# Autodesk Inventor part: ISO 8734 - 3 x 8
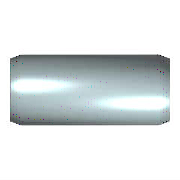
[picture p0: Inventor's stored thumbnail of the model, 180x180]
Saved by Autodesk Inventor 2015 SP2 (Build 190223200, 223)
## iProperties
Created: 2012-02
Part Number: ISO 8734 - 3 x 8
Material: Stahl
Description: Zylinderstifte aus gehärtetem Martensit-Edelstahl (Passstifte)
Document SubType Name: Modeling
Standard: ISO 8734
Designer: rYan
Standards Organization: BSI
Language: de-DE
Size Designation: 3 x 8
Categories: <MemberInstance><Categories><Category DisplayName="Verbindungselemente" InternalName="e4da775c-781d-43d5-af7c-5136215cf5a6" Mnemonic="FSTN"><Category DisplayNam
Density: 7.85 g/cm^3
Appearance: Platte
IsCustomPart: 1
Author: rYan
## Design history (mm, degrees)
sketch "Skizze"
  geometry: C1 r 1.5 at (0, 0); 1 further point
  constraints: 1 centre point, 1 coincident
  dimensions: "d1" = 3 diameter of C1 (= NND)
extrude "Körper" new body sketch "Skizze" distance "d2" = 6; taper "d3" = 0 deg
chamfer "Skizze2" distance "d8" = 0.5 (= PHH); stored, may be unused: angle "d9" = 15 deg (= FAWI), second distance "d12" = 0.5 (= PHH)
body "Solid1"
chamfer "Fase1" distance "d4" = 0.5 (= PHH); stored, may be unused: angle "d5" = 15 deg (= FAWI), second distance "d11" = 0.5 (= PHH)
other parameters: "NND" = 3 [user parameter; used in 1 equation term], "NLG" = 8 [user parameter], "PHH" = 0.5 [user parameter; used in 5 equation terms], "FAWI" = 15 deg [user parameter; used in 2 equation terms], "d13" = 0, "d15" = 0, "d16" = 0, "PHH2" = 0.5 (= PHH) [user parameter], "FAWI2" = 15 deg [user parameter]
